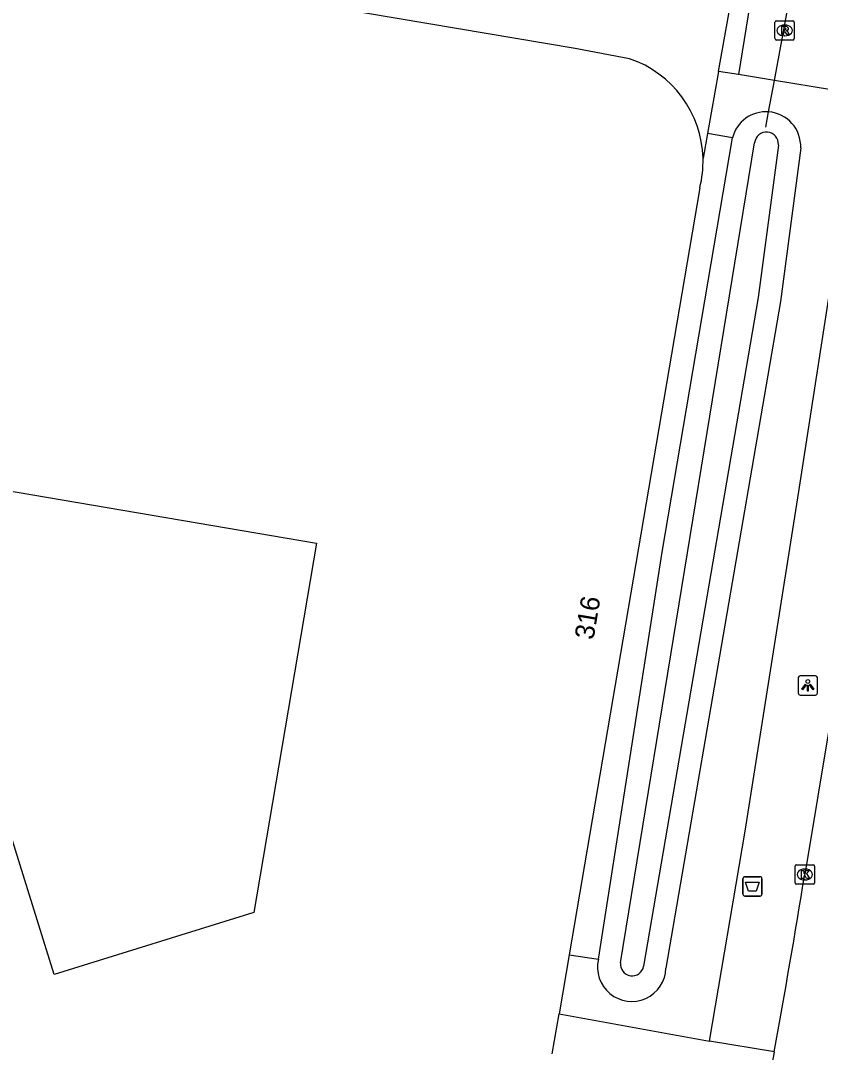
# Model space of a CAD drawing. Extents: x 161094 to 161705, y 379509 to 380907.
# Drawn here: x 161482.5 to 161524, y 379865.7 to 379919.3 of the extents above; entities that cross this region are included whole.
import ezdxf

# ---------------------------------------------------------------- set-up
doc = ezdxf.new("R2010")
doc.units = 0
for name, color, linetype in [('IMGEO_Afvalbak', 7, 'Continuous'), ('IMGEO_Duiker', 7, 'Continuous'), ('IMGEO_Groenvoorziening', 7, 'Continuous'), ('IMGEO_Kolk', 7, 'Continuous'), ('IMGEO_Lichtpunt', 7, 'Continuous'), ('IMGEO_OVBaan_gesloten', 7, 'Continuous'), ('IMGEO_Pand', 7, 'Continuous'), ('IMGEO_Pand_nummerreeks', 7, 'Continuous'), ('IMGEO_Rijbaan_lokaal_open', 7, 'Continuous'), ('IMGEO_Rioolput', 7, 'Continuous'), ('IMGEO_Voetpad_open', 7, 'Continuous'), ('IMGEO_Waterloop', 7, 'Continuous')]:
    doc.layers.add(name, color=color, linetype=linetype)

msp = doc.modelspace()

# ---------------------------------------------------------------- linework, layer by layer
at = {"layer": 'IMGEO_Afvalbak'}
for p, q in [((161520.121, 379874.824), (161520.911, 379874.824)), ((161520.911, 379874.824), (161520.121, 379874.824)), ((161520.021, 379873.924), (161520.021, 379874.724)), ((161520.021, 379874.724), (161520.021, 379873.924)), ((161521.011, 379874.724), (161521.011, 379873.924)), ((161521.011, 379873.924), (161521.011, 379874.724)), ((161520.911, 379873.824), (161520.121, 379873.824)), ((161520.121, 379873.824), (161520.911, 379873.824))]:
    msp.add_line(p, q, dxfattribs=at)
msp.add_lwpolyline([(161520.164, 379874.538), (161520.868, 379874.538), (161520.719, 379874.068), (161520.313, 379874.068), (161520.164, 379874.538)], dxfattribs=at)
for centre, start, end in [((161520.121, 379874.724), 90, 180), ((161520.121, 379874.724), 90, 180), ((161520.911, 379874.724), 0, 90), ((161520.911, 379874.724), 360, 90), ((161520.121, 379873.924), 180, 270), ((161520.121, 379873.924), 180, 270), ((161520.911, 379873.924), 270, 0), ((161520.911, 379873.924), 270, 0)]:
    msp.add_arc(centre, 0.1, start, end, dxfattribs=at)
at = {"layer": 'IMGEO_Duiker'}
msp.add_lwpolyline([(161521.213, 379913.764), (161521.359, 379914.557), (161521.659, 379916.19), (161523.289, 379925.051), (161523.456, 379925.959), (161523.636, 379926.94)], dxfattribs=at)
at = {"layer": 'IMGEO_Groenvoorziening'}
for points in [[(161519.482, 379913.207), (161518.179, 379913.425)], [(161512.517, 379870.541), (161515.837, 379891.688), (161519.482, 379913.207)], [(161523.024, 379912.682), (161521.974, 379904.714), (161516.028, 379870.076)], [(161511, 379870.768), (161512.517, 379870.541)]]:
    msp.add_lwpolyline(points, dxfattribs=at)
for centre, radius, start, end in [((161521.226, 379912.762), 1.8, 85.7538, 165.6961), ((161521.227, 379912.763), 1.799, 357.4168, 85.7933), ((161514.248, 379870.127), 1.78, 166.5509, 358.3603)]:
    msp.add_arc(centre, radius, start, end, dxfattribs=at)
at = {"layer": 'IMGEO_Kolk'}
for p, q in [((161522.738, 379874.516), (161522.738, 379875.368)), ((161522.813, 379875.442), (161523.665, 379875.442)), ((161523.739, 379875.368), (161523.739, 379874.516)), ((161523.226, 379875.222), (161523.251, 379875.222)), ((161523.665, 379874.442), (161522.813, 379874.442)), ((161523.249, 379874.662), (161523.224, 379874.662))]:
    msp.add_line(p, q, dxfattribs=at)
for points in [[(161522.738, 379874.516), (161522.738, 379875.368)], [(161522.813, 379875.442), (161523.665, 379875.442)], [(161523.739, 379875.368), (161523.739, 379874.516)], [(161523.059, 379875.142), (161523.182, 379875.142), (161523.182, 379874.991), (161523.312, 379875.142), (161523.476, 379875.142), (161523.33, 379874.991), (161523.483, 379874.742), (161523.331, 379874.742), (161523.246, 379874.906), (161523.182, 379874.839), (161523.182, 379874.742), (161523.059, 379874.742), (161523.059, 379875.142)], [(161523.665, 379874.442), (161522.813, 379874.442)]]:
    msp.add_lwpolyline(points, dxfattribs=at)
for centre, start, end in [((161522.815, 379875.366), 91.552, 178.448), ((161522.815, 379875.366), 91.552, 178.448), ((161523.663, 379875.366), 1.552, 88.448), ((161523.663, 379875.366), 1.552, 88.448), ((161522.815, 379874.518), 181.552, 268.448), ((161522.815, 379874.518), 181.552, 268.448), ((161523.663, 379874.518), 271.552, 358.448), ((161523.663, 379874.518), 271.552, 358.448)]:
    msp.add_arc(centre, 0.0765, start, end, dxfattribs=at)
for centre, major_axis, ratio, start_param, end_param in [((161523.225, 379874.942), (-0.387, 0.002), 0.722429, 4.712389, 7.853982), ((161523.25, 379874.942), (-0.39, 0.002), 0.717154, 1.570796, 4.712389)]:
    msp.add_ellipse(centre, major_axis=major_axis, ratio=ratio, start_param=start_param, end_param=end_param, dxfattribs=at)
at = {"layer": 'IMGEO_Lichtpunt'}
for p, q in [((161522.895, 379885.166), (161522.895, 379884.359)), ((161522.895, 379885.166), (161522.895, 379884.359)), ((161523.797, 379885.261), (161522.989, 379885.261)), ((161523.797, 379885.261), (161522.989, 379885.261)), ((161523.891, 379884.359), (161523.891, 379885.166)), ((161523.891, 379884.359), (161523.891, 379885.166)), ((161522.989, 379884.265), (161523.797, 379884.265)), ((161522.989, 379884.265), (161523.797, 379884.265))]:
    msp.add_line(p, q, dxfattribs=at)
for points in [[(161523.269, 379884.83), (161523.308, 379884.802), (161523.12, 379884.54), (161523.082, 379884.567), (161523.269, 379884.83)], [(161523.371, 379884.782), (161523.418, 379884.782), (161523.418, 379884.46), (161523.371, 379884.46), (161523.371, 379884.782)], [(161523.481, 379884.802), (161523.519, 379884.829), (161523.706, 379884.567), (161523.667, 379884.539), (161523.481, 379884.802)]]:
    msp.add_lwpolyline(points, dxfattribs=at)
msp.add_circle((161523.394, 379884.964), 0.0994, dxfattribs=at)
for centre, start, end in [((161522.989, 379885.166), 90, 180), ((161522.989, 379885.166), 90, 180), ((161523.797, 379885.166), 0, 90), ((161523.797, 379885.166), 0, 90), ((161522.989, 379884.359), 180, 270), ((161522.989, 379884.359), 180, 270), ((161523.797, 379884.359), 270, 0), ((161523.797, 379884.359), 270, 360)]:
    msp.add_arc(centre, 0.0946, start, end, dxfattribs=at)
at = {"layer": 'IMGEO_OVBaan_gesloten'}
msp.add_lwpolyline([(161527.971, 379905.065), (161526.727, 379897.107), (161524.592, 379883.079), (161523.239, 379874.942)], dxfattribs=at)
for centre, radius, start, end in [((160912.449, 379975.076), 618.943, 349.823773, 350.689677), ((160897.259, 379977.712), 634.361, 349.399884, 349.831828)]:
    msp.add_arc(centre, radius, start, end, dxfattribs=at)
at = {"layer": 'IMGEO_Pand'}
for points in [[(161514.139, 379917.319), (161511.311, 379917.848), (161457.045, 379927.006)], [(161517.782, 379910.612), (161511, 379870.768)], [(161497.881, 379892.147), (161494.617, 379872.972), (161484.258, 379869.742), (161476.118, 379895.851), (161497.881, 379892.147)], [(161511, 379870.768), (161510.477, 379867.696)], [(161510.124, 379865.623), (161510.477, 379867.696)]]:
    msp.add_lwpolyline(points, dxfattribs=at)
for centre, radius, start, end in [((161512.324, 379911.99), 5.629, 1.5838, 71.1895), ((161512.293, 379911.993), 5.661, 345.8782, 1.548)]:
    msp.add_arc(centre, radius, start, end, dxfattribs=at)
at = {"layer": 'IMGEO_Rijbaan_lokaal_open'}
for points in [[(161518.754, 379916.647), (161520.33, 379925.471)], [(161521.239, 379925.396), (161519.795, 379916.496)], [(161518.754, 379916.647), (161518.179, 379913.425)], [(161519.795, 379916.496), (161518.754, 379916.647)], [(161524.623, 379915.703), (161521.659, 379916.19), (161519.795, 379916.496)], [(161518.179, 379913.425), (161517.951, 379912.146)]]:
    msp.add_lwpolyline(points, dxfattribs=at)
at = {"layer": 'IMGEO_Rioolput'}
for p, q in [((161521.765, 379919.286), (161522.617, 379919.286)), ((161521.69, 379918.36), (161521.69, 379919.212)), ((161522.178, 379919.066), (161522.203, 379919.066)), ((161522.691, 379919.212), (161522.691, 379918.36)), ((161522.617, 379918.286), (161521.765, 379918.286)), ((161522.201, 379918.506), (161522.176, 379918.506))]:
    msp.add_line(p, q, dxfattribs=at)
for points in [[(161521.765, 379919.286), (161522.617, 379919.286)], [(161521.69, 379918.36), (161521.69, 379919.212)], [(161522.279, 379918.984), (161522.027, 379918.986), (161522.027, 379918.586)], [(161522.027, 379918.586), (161522.151, 379918.586), (161522.151, 379918.748), (161522.162, 379918.748)], [(161522.205, 379918.905), (161522.151, 379918.905), (161522.151, 379918.824)], [(161522.151, 379918.824), (161522.203, 379918.824)], [(161522.691, 379919.212), (161522.691, 379918.36)], [(161522.617, 379918.286), (161521.765, 379918.286)], [(161522.209, 379918.719), (161522.28, 379918.586), (161522.42, 379918.586), (161522.355, 379918.712)]]:
    msp.add_lwpolyline(points, dxfattribs=at)
for centre, radius, start, end in [((161521.767, 379919.21), 0.0765, 91.552, 178.448), ((161521.767, 379919.21), 0.0765, 91.552, 178.448), ((161522.615, 379919.21), 0.0765, 1.552, 88.448), ((161522.615, 379919.21), 0.0765, 1.552, 88.448), ((161522.161, 379918.695), 0.0533, 26.0293, 88.6989), ((161522.187, 379919.013), 0.19, 274.7715, 282.9687), ((161522.211, 379918.809), 0.0964, 77.0061, 93.1865), ((161522.225, 379918.866), 0.0378, 276.6634, 79.6772), ((161522.278, 379918.874), 0.109, 350.3612, 89.416), ((161522.276, 379918.874), 0.112, 277.5842, 350.9817), ((161522.26, 379918.659), 0.108, 29.5134, 73.7905), ((161521.767, 379918.362), 0.0765, 181.552, 268.448), ((161521.767, 379918.362), 0.0765, 181.552, 268.448), ((161522.615, 379918.362), 0.0765, 271.552, 358.448), ((161522.615, 379918.362), 0.0765, 271.552, 358.448)]:
    msp.add_arc(centre, radius, start, end, dxfattribs=at)
for centre, major_axis, ratio, start_param, end_param in [((161522.177, 379918.786), (-0.387, 0.002), 0.722429, 4.712389, 7.853982), ((161522.202, 379918.786), (-0.39, 0.002), 0.717154, 1.570796, 4.712389)]:
    msp.add_ellipse(centre, major_axis=major_axis, ratio=ratio, start_param=start_param, end_param=end_param, dxfattribs=at)
at = {"layer": 'IMGEO_Voetpad_open'}
for points in [[(161518.281, 379866.292), (161520.143, 379877.191), (161522.931, 379894.837), (161524.586, 379905.575), (161527.971, 379905.065)], [(161510.477, 379867.696), (161518.281, 379866.292)], [(161521.656, 379865.723), (161518.281, 379866.292)]]:
    msp.add_lwpolyline(points, dxfattribs=at)
at = {"layer": 'IMGEO_Waterloop'}
for points in [[(161513.673, 379870.36), (161520.632, 379912.951)], [(161521.864, 379912.835), (161520.821, 379904.912), (161514.867, 379870.178)]]:
    msp.add_lwpolyline(points, dxfattribs=at)
for centre, radius, start, end in [((161521.248, 379912.889), 0.619, 355.0393, 174.203), ((161514.271, 379870.278), 0.604, 172.2126, 350.4538)]:
    msp.add_arc(centre, radius, start, end, dxfattribs=at)

# ---------------------------------------------------------------- texts
at = {"layer": 'IMGEO_Pand_nummerreeks'}
msp.add_text('316', height=1, rotation=80.3401, dxfattribs=at).set_placement((161512.258, 379887.102))

doc.saveas('drawing.dxf')
